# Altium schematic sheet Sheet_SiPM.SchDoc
size A4; SheetNumber: 1; SheetTotal: 1
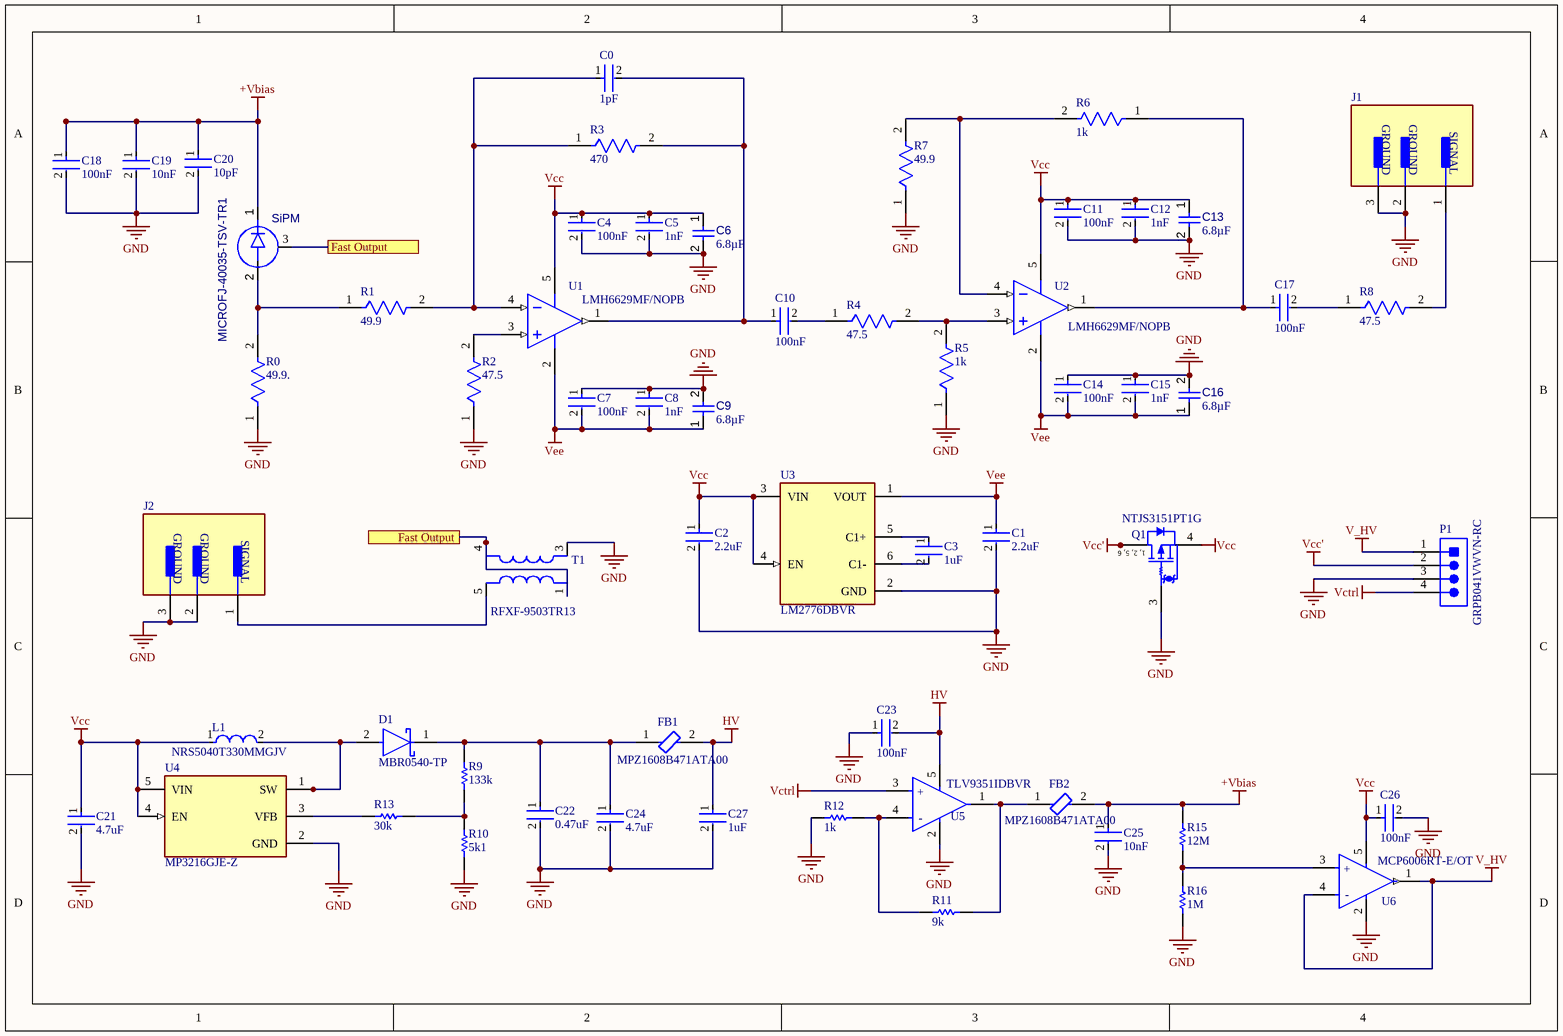
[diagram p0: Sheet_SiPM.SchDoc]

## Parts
C0  1pF  [FP-0603-L_1_6_0_15-W_0_81-MFG]
C1  2.2uF  [FP-GRM188-0_2-MFG]
C2  2.2uF  [FP-GRM188-0_2-MFG]
C3  1uF  [FP-CC0603-DA-MFG]
C4  100nF  [FP-CC0603-DA-MFG]
C5  1nF  [FP-CC0603-DA-MFG]
C6  value 6.8µF  [TPSA685K016R1500-Footprint-1]  (hidden comment: TPSA685K016R1500)
C7  100nF  [FP-CC0603-DA-MFG]
C8  1nF  [FP-CC0603-DA-MFG]
C9  value 6.8µF  [TPSA685K016R1500-Footprint-1]  (hidden comment: TPSA685K016R1500)
C10  100nF  [FP-CC0603-DA-MFG]
C11  100nF  [FP-CC0603-DA-MFG]
C12  1nF  [FP-CC0603-DA-MFG]
C13  value 6.8µF  [TPSA685K016R1500-Footprint-1]  (hidden comment: TPSA685K016R1500)
C14  100nF  [FP-CC0603-DA-MFG]
C15  1nF  [FP-CC0603-DA-MFG]
C16  value 6.8µF  [TPSA685K016R1500-Footprint-1]  (hidden comment: TPSA685K016R1500)
C17  100nF  [FP-CC0603-DA-MFG]
C18  100nF  [FP-CC0603-DA-MFG]
C19  10nF  [FP-CC0603-DA-MFG]
C20  10pF  [FP-AC0603-MFG]
C21  4.7uF  [FP-0603-L_1_6_0_1-W_0_8_0-MFG]
C22  0.47uF  [FP-0603-L_1_6_0_1-W_0_8_0-MFG]
C23  100nF  [FP-CC0603-DA-MFG]
C24  4.7uF  [FP-0603-L_1_6_0_15-W_0_8-MFG]
C25  10nF  [FP-CC0603-DA-MFG]
C26  100nF  [FP-CC0603-DA-MFG]
C27  1uF  [FP-CC0603-DA-MFG]
D1  MBR0540-TP  [FP-SOD-123-MFG]
FB1  MPZ1608B471ATA00  [FP-MPZ1608-0_8-MFG]
FB2  MPZ1608B471ATA00  [FP-MPZ1608-0_8-MFG]
J1  2337019-1  [FP-2337019-1-MFG]  (value not drawn)
J2  2337019-1  [FP-2337019-1-MFG]  (value not drawn)
L1  NRS5040T330MMGJV  [FP-NR5040-H_4_0-MFG]
P1  GRPB041VWVN-RC  [SLIN-GRPB041VWVN-RC_V]
Q1  NTJS3151PT1G  [ONSC-SC70-6-419B-02_W_V]
R0  49.9.  [FP-RNCP0603-MFG]
R1  49.9  [FP-RNCP0603-MFG]
R2  47.5  [FP-RNCP0603-MFG]
R3  470  [FP-MCT0603-MFG]
R4  47.5  [FP-RNCP0603-MFG]
R5  1k  [FP-MCT0603-MFG]
R6  1k  [FP-MCT0603-MFG]
R7  49.9  [FP-RNCP0603-MFG]
R8  47.5  [FP-RNCP0603-MFG]
R9  133k  [RESC2013X60X35LL10T20]
R10  5k1  [RESC2013X60X35LL10T20]
R11  9k  [RESC2013X60X35LL10T20]
R12  1k  [RESC2013X60X35LL10T20]
R13  30k  [RESC2013X60X35LL10T20]
R15  12M  [RESC2013X60X35LL10T20]
R16  1M  [RESC2013X60X35LL10T20]
SiPM  MICROFJ-40035-TSV-TR1
T1  RFXF-9503TR13  [RFXF-9503TR13-Footprint-1]
U1  LMH6629MF/NOPB  [DBV0005A_L]
U2  LMH6629MF/NOPB  [DBV0005A_L]
U3  LM2776DBVR  [FP-DBV0006A-MFG]
U4  MP3216GJE-Z  [MP3216GJE-Z-Footprint-1]
U5  TLV9351IDBVR  [FP-DBV0005A-MFG]
U6  MCP6006RT-E/OT  [FP-C04-091-OT-MFG]

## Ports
Fast Output (see Sheet_SiPM[1A]), Fast Output (see Sheet_SiPM[1C])

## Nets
+Vbias: C18.1 C19.1 C20.1 C25.1 FB2.2 R15.2 SiPM.1(K)
GND: C1.2 C2.2 C4.2 C5.2 C6.2 C7.1 C8.1 C9.2 C11.2 C12.2 C13.2 C14.1 C15.1 C16.2 C18.2 C19.2 C20.2 C21.2 C22.2 C23.1 C24.2 C25.2 C26.2 C27.2 J1.2(GROUND) J1.3(GROUND) J2.2(GROUND) J2.3(GROUND) P1.3 Q1.3(G) R0.1 R2.1 R5.1 R7.1 R10.1 R12.2 R16.1 T1.3 U3.2(GND) U4.2(GND) U5.2(V-) U6.2(VSS)
HV: C23.2 C27.1 FB1.2 U5.5(V+)
V_HV: P1.1 U6.1(VOUT) U6.4(VIN-)
Vcc: C2.1 C4.1 C5.1 C6.1 C11.1 C12.1 C13.1 C21.1 C26.1 L1.1 Q1.4(S) U1.5(V+) U2.5(V+) U3.3(VIN) U3.4(EN) U4.4(EN) U4.5(VIN) U6.5(VDD)
Vcc': P1.2 Q1.1(D) Q1.2(D) Q1.5(D) Q1.6(D)
Vctrl: P1.4 U5.3(IN+)
Vee: C1.1 C7.2 C8.2 C9.1 C14.2 C15.2 C16.1 U1.2(V-) U2.2(V-) U3.1(VOUT)
Fast Output: SiPM.3(F) T1.1 T1.4 ; port Fast Output
NetC0_1: C0.1 R1.2 R3.1 U1.4(IN-)
NetC0_2: C0.2 C10.1 R3.2 U1.1(OUT)
NetC3_1: C3.1 U3.5(C1+)
NetC3_2: C3.2 U3.6(C1-)
NetC10_2: C10.2 R4.1
NetC17_1: C17.1 R6.1 U2.1(OUT)
NetC17_2: C17.2 R8.1
NetC22_1: C22.1 C24.1 D1.1(C) FB1.1 R9.2
NetD1_2: D1.2(A) L1.2 U4.1(SW)
NetFB2_1: FB2.1 R11.1 U5.1(OUT)
NetJ1_1: J1.1(SIGNAL) R8.2
NetJ2_1: J2.1(SIGNAL) T1.5
NetR0_2: R0.2 R1.1 SiPM.2(A)
NetR2_2: R2.2 U1.3(IN+)
NetR4_2: R4.2 R5.2 U2.3(IN+)
NetR6_2: R6.2 R7.2 U2.4(IN-)
NetR9_1: R9.1 R10.2 R13.1
NetR11_2: R11.2 R12.1 U5.4(IN-)
NetR13_2: R13.2 U4.3(VFB)
NetR15_1: R15.1 R16.2 U6.3(VIN+)

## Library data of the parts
C0 = CMP-2006-04257-2: General Purpose Ceramic Capacitor, 0603, 1pF, 0.1pF, NP0, 30ppm/°C, 50V; Dielectric: C0G
C1 C2 = CMP-06035-057307-1: Chip Multilayer Ceramic Capacitors for General Purpose, 0603, 2.2uF, X7R, 15%, 10%, 16V
C3 = CMP-03422-000924-1: CAP CER 1UF 16V X7R 0603; Manufacturer: YAGEO; Manufacturer Part Number: CC0603KRX7R7BB105; Tolerance: 0.1; Temperature Coefficient: 15%; Material: Ceramic
C4 C7 C10 C11 C14 C17 C26 = CMP-2000-05002-2: CAP CER 0.1UF 16V X7R 0603; Manufacturer Part Number: CC0603KRX7R7BB104; Manufacturer: YAGEO; Tolerance: 0.1; Temperature Coefficient: 15%; Material: Ceramic
C5 C8 C12 C15 = CMP-03422-001144-1: CAP CER 1000PF 25V X7R 0603; Manufacturer: YAGEO; Manufacturer Part Number: CC0603KRX7R8BB102; Value: 1.0 nF; Material: Ceramic; Temperature Coefficient: 15%; Tolerance: 0.1
C6 C9 C13 C16 = CMP-001-00083-2: Tantalum Capacitor, Polarized, Tantalum (dry/solid), 16V, 10% +Tol, 10% -Tol, 6.8uF, Surface Mount, 1206
C18 C23 = CMP-2100-03601-2: CAP CER 0.1UF 50V X7R 0603; Manufacturer: YAGEO; Manufacturer Part Number: CC0603KRX7R9BB104; Material: Ceramic; Temperature Coefficient: 15%; Tolerance: 0.1
C19 C25 = CMP-2100-03600-2: CAP CER 10000PF 50V X7R 0603; Manufacturer Part Number: CC0603KRX7R9BB103; Manufacturer: YAGEO; Tolerance: 0.1; Material: Ceramic; Temperature Coefficient: 15%
C20 = CMP-03422-001295-1: AC0603 10 pF NP0 1.00% 50 V; Manufacturer: Yageo; Manufacturer Part Number: AC0603FRNPO9BN100; Voltage Rating: 50 V; Material: Ceramic; Temperature Coefficient: 15%; Automotive Grade: Grade 1; Tolerance: 0.01
C21 C22 = CMP-14477-000135-3: Ceramic Capacitor General Use 0.47uF ±10% 50V X7R 0603; NexarPartId: 22313259; Capacitance: 470nF
C24 = CMP-2000-07531-4: Ceramic Capacitor General Use 1uF ±10% 50V X7R 0603
C27 = CMP-2100-03600-2: CAP CER 10000PF 50V X7R 0603; Manufacturer Part Number: CC0603KRX7R9BB103; Manufacturer: YAGEO; Tolerance: 0.1; Material: Ceramic; Temperature Coefficient: 15%; Value: 10 nF
D1 = CMP-2000-06672-2: DIODE SCHOTTKY 40V 500MA SOD123; Polarity: Standard; Peak Non-Repetitive Surge Current: 5.5A; Forward Voltage: 550mV; Peak Reverse Current: 200uA; Element Configuration: Single; Capacitance: 30pF
FB1 FB2 = CMP-08257-000382-1: Power line Ferrite Bead 470Ω @ 100MHz 1A DCR 0.15Ω SMD 0603; DC Resistance (DCR): 150mR; Impedance: 470R; Tolerance: 25%
J1 J2 = CMP-03357-000011-1: UMCC MICRO-COAX RECEPTACLE, GEN
L1 = CMP-14484-000440-1: SMD Power Inductors for Automotive Applications 33uH ±20% 1.2A 0.234Ω; Core Material: Ferrite; Self Resonant Frequency: 7MHz; Shielding: Shielded; Test Frequency: 100kHz; Saturation Current: 1.3A; DC Resistance (DCR): 234mR
P1 = CMP-2000-06373-1: Male Header, Pitch 1.27 mm, 1 x 4 Position, Height 4 mm, Tail Length 2.3 mm, -40 to 105 degC, RoHS, Bulk; Manufacturer: Sullins; Mating Products: S9010E-04-ND / -CONNHEADER.050"4POSR/APCB / S9008E-04-ND / -CONNHEADER.050"4POSPCBGOLD / S9005E-04-ND / -CONNHEADER.050"4POSSMDGOLD; Other Names: S9014E-04; Dynamic Catalog: GRPB; Pitch: 0.050"(1.27mm); Number of Positions Loaded: All; Number of Positions: 4; Catalog Drawings: S9014ESeriesTop; Connector Type: Header,Unshrouded
Q1 = CMP-1058-00634-1: Trench Power MOSFET, 12 V, 3.3 A, Single P-Channel, ESD Protected, 6-Pin SC70, Pb-Free, Tape and Reel; Manufacturer: On Semiconductor; PD Max (W): 0.625; Coss Typ (pF): 170; Channel Polarity: P Channel; V(BR)DSS Min (V): 12; ID Max (A): 3.3; Ciss Typ (pF): 850; Crss Typ (pF): 110
R0 R1 R7 = CMP-26527-005229-1: 49.9Ω ±1% 0.125W 0603 High Power Anti-Sulfur Thin Film Chip Resistor; Temperature Coefficient: 100ppm/°C; Resistance: 49.9R; Max Power Dissipation: 125mW
R2 R4 R8 = CMP-26527-005114-1: 47.5Ω ±1% 0.125W 0603 High Power Anti-Sulfur Thin Film Chip Resistor; Temperature Coefficient: 100ppm/°C; Resistance: 47.5R; Max Power Dissipation: 125mW
R3 = CMP-02407-000044-1: RES SMD 100 OHM 1% 1/8W 0603; Resistance: 470R; Temperature Coefficient: 50ppm/°C; Voltage Rating (DC): 75V; Max Power Dissipation: 125mW
R5 R6 = CMP-02407-005727-1: RES SMD 100 OHM 1% 1/8W 0603; Max Power Dissipation: 100mW; Resistance: 1kR; Temperature Coefficient: 50ppm/°C
R9 R11 R12 R15 R16 = CMP-2001-00968-1: Manufacturer: Yageo; Part Number: RC0805FR-071M05L
R10 R13 = CMP-2001-01383-1: Manufacturer: Yageo; Part Number: RC0805JR-0743KL
SiPM = CMP-004-00031-2: Avalanche Photodiode
T1 = CMP-012-00000-1: SMT Transformer 3MHZ-3GHZ
U1 U2 = CMP-0055-01252-3: Single/ Dual Ultra Low Noise Wideband Operational Amplifier, 5-pin SOT-23, Pb-Free; Manufacturer: Texas Instruments; CompType: Amplifiers; PowerWise: Y; PackageTopMarking: A94A*XTT
U3 = CMP-04918-000109-1: IC REG CHARGE PUMP INV SOT23; Manufacturer: Texas Instruments; Nominal Supply Current: 100uA; Switching Frequency: 2MHz; Number Of Outputs: 1; Standoff Height: 0mm; Min Supply Voltage: 2.7V; Output Current: 200mA; Max Supply Voltage: 5.5V; Output Type: Fixed; Max Junction Temp: +125°C; Negative Voltage Available: true; Output Voltage: -2.7-5.5V
U4 = CMP-00024-00006-1: Switching Regulator
U5 = CMP-04895-000384-1: OPAMP
U6 = CMP-00252-117321646-1: MCP6006RT-E/OT Operational Amplifier, 1 Func, 1600uV Offset-Max, CMOS, PDSO5; Number of Channels: 1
